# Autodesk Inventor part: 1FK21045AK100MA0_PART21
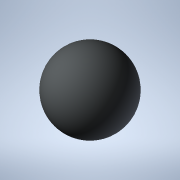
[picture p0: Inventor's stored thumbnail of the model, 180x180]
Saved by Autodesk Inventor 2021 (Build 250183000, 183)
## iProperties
Created: 2025-04
Part Number: 1FK21045AK100MA0_PART21
Material: Generic
Catalog Web Link: www.3dfindit.com
Description: -Servo synchronous motor
Document SubType Name: Modeling
Designer: psAdmin
Mass: 0.137258 g
Surface Area: 1.2868 cm^2
Volume: 0.137258 cm^3
Density: 1 g/cm^3
Appearance: PSOLRGB-212-217-219
Category: PARTsolutions
Title: 1FK21045AK100MA0_PART21
Author: Cadenas PARTsolutions
Comments: Servo synchronous motor
Sending System: PARTsolutions
Preprocessor: ST-DEVELOPER v19.3
PSOL_IDENT_0: {$CADENAS_DATA/23d-libs/siemens_ag/_cat_/e0/5f/1fk21045ak100ma0.prj},216 {VTYP=3D},{NB=1FK21045AK100
PSOL_IDENT_1: MA0_PART21},{LINA=1FK21045AK100MA0_PART21},{NN=1FK21045AK100MA0_PART21},{NOPRJ=TRUE},{DATE=19.08.202
PSOL_IDENT_2: 5 14:01:03},{GEOMDATE=30.07.2025 02:01:57},{VERSION=},{LINEID=10},{WBVAR=},{WBNUMERIC=}  {NB=1FK2104
PSOL_IDENT_3: 5AK100MA0_PART21},{LINA=1FK21045AK100MA0_PART21},{KT=DUMMY},{PREVIEW=../../../_pool_/0f/2c/p_d211_xx
PSOL_IDENT_4: _00438j.png},{DESCSHORT=SIMOTICS S-1FK2 HD, SINAMICS S210 3AC 400V-480V, 1.7 Nm, 6000 rpm},{DESCLONG=
PSOL_IDENT_5: SIMOTICS S-1FK2 HD servo motor M0=2.4 Nm; PN = 1.07 kW at nN=6000 rpm (380-480 V); PN = 0.75 kW at n
PSOL_IDENT_6: N=3000 rpm (200-240 V); with holding brake; degree of protection IP64; cylindrical shaft D19x40mm; a
PSOL_IDENT_7: bsolute encoder 22-bit + 12-bit multiturn (encoder AM22DQC); with OCC interface; plug size M17, rota
PSOL_IDENT_8: table; SIMOTICS S-1FK2 servomotorfor a wide range of uses in industrial environments. SIMOTICS S‑1FK
PSOL_IDENT_9: 2 servomotors are compact synchronous motors with a high dynamic performance that set themselves apa
PSOL_IDENT_10: rt as a result of their high power density, degree of protection and overload capability. The motors
PSOL_IDENT_11: are available in two variants: as High Dynamic variant (highest dynamic performance as a result of
PSOL_IDENT_12: the low intrinsic moment of inertia for applications demanding a high dynamic performance with low m
PSOL_IDENT_13: oved masses) - and as Compact variant (precise and stable closed-loop control for medium up to large
PSOL_IDENT_14: moved masses as a result of a medium intrinsic moment of inertia). SIMOTICSS‑1FK2 servomotors fully
PSOL_IDENT_15: exploit their strengths in a system with the SINAMICSS210 frequency converter and simple connection
PSOL_IDENT_16: using the one cable connection (OCC). Advantages include the short control and positioning times, f
PSOL_IDENT_17: ast and precise correction of disturbing quantities as well as stable control with a high dynamic pe
PSOL_IDENT_18: rformance. The servo motors can be configured to address a wide range of requirements. For example w
PSOL_IDENT_19: ith and without holding brake, IP64 or IP65 degree of protection, singleturn or multiturn absolute e
PSOL_IDENT_20: ncoders - to name just a few. Further, the servomotors are available in different shaft heights exte
PSOL_IDENT_21: nding from 20 to 100. A shaft sealing ring is available to achieve an IP65 degree of protection and
PSOL_IDENT_22: for subsequent mounting at the motor or as spare part. SIMOTICS - the optimum motor for each and eve
PSOL_IDENT_23: ry motion control application.},{INTNO=804766807114},{SUPPLIERALTNO=1FK2104-5AK10-0MA0},{MANUID=1FK2
PSOL_IDENT_24: 1045AK100MA0},{MANUNAME=Siemens},{MANUTYPEDESC=Synchronous motor 1FK2-HD 2,39 Nm},{AAU732=SIMOTICS},
PSOL_IDENT_25: {AAO057=S-1FK2},{AAU734=SIMOTICS S-1FK2 HD servo motor M0=2.4 Nm; PN = 1.07 kW at nN=6000 rpm (380-4
PSOL_IDENT_26: 80 V); PN = 0.75 kW at nN=3000 rpm (200-240 V); with holding brake; degree of protection IP64; cylin
PSOL_IDENT_27: drical shaft D19x40mm; absolute encoder 22-bit + 12-bit multiturn (encoder AM22DQC); with OCC interf
PSOL_IDENT_28: ace; plug size M17, rotatable;},{AAW338=Synchronous motor 1FK2-HD 2,39 Nm},{AAO742=SIMOTICS},{AAO663=
PSOL_IDENT_29: 4042948691236},{NOCUPEROU=1},{PRICEQUANTITY=1},{QUANTITYMIN=1},{QUANTITYINT=1},{CTN=85015100},{COO=D
PSOL_IDENT_30: E},{AAO676=1FK2104-5AK10-0MA0},{AAO677=Siemens AG},{ORDERUNIT=C62},{CONTENTUNIT=C62}
NB: 1FK21045AK100MA0_PART21
NT: Servo synchronous motor
NBSYN: $MANUID._PART21
LINA: 1FK21045AK100MA0_PART21
CATALOG: SIEMENS
PREVIEW: ../../../_pool_/0f/2c/p_d211_xx_00438j.png
DESCSHORT: SIMOTICS S-1FK2 HD, SINAMICS S210 3AC 400V-480V, 1.7 Nm, 6000 rpm
DESCLONG: SIMOTICS S-1FK2 HD servo motor M0=2.4 Nm; PN = 1.07 kW at nN=6000 rpm (380-480 V); PN = 0.75 kW at nN=3000 rpm (200-240 V); with holding brake; degree of protec
INTNO: 804766807114
SUPPLIERALTNO: 1FK2104-5AK10-0MA0
MANUID: 1FK21045AK100MA0
MANUNAME: Siemens
MANUTYPEDESC: Synchronous motor 1FK2-HD 2,39 Nm
AAU732: SIMOTICS
AAO057: S-1FK2
AAU734: SIMOTICS S-1FK2 HD servo motor M0=2.4 Nm; PN = 1.07 kW at nN=6000 rpm (380-480 V); PN = 0.75 kW at nN=3000 rpm (200-240 V); with holding brake; degree of protec
AAW338: Synchronous motor 1FK2-HD 2,39 Nm
AAO742: SIMOTICS
AAO663: 4042948691236.0
NOCUPEROU: 1
PRICEQUANTITY: 1
QUANTITYMIN: 1
QUANTITYINT: 1
CTN: 85015100
COO: DE
ARTICLENO: 1FK21045AK100MA0_PART21
BOMINFO: 1FK21045AK100MA0_PART21
CREATOR: CADENAS GmbH
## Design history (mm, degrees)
feature "2025_04_17_15_45_15_0090"
body "Solid1"
